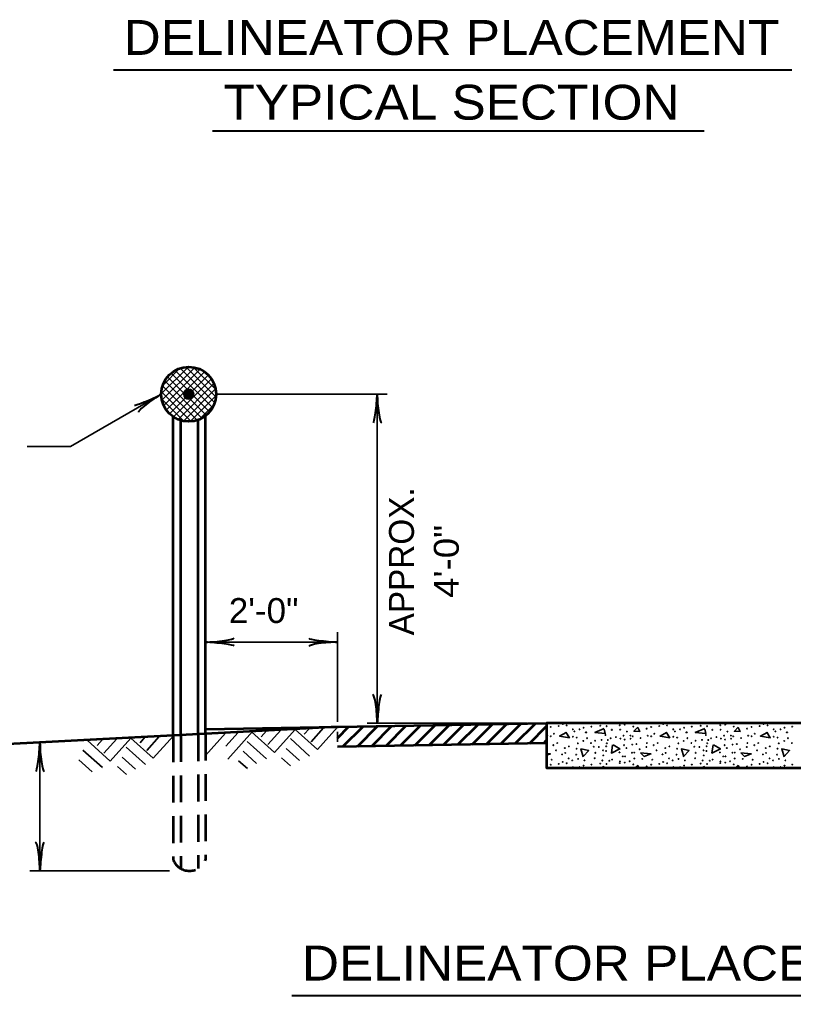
# Model space of a CAD drawing. Extents: x -54 to 626, y -41 to 399.
# Drawn here: x 39.2 to 116.9, y 192.7 to 290.7 of the extents above; entities that cross this region are included whole.
import ezdxf
from ezdxf.enums import TextEntityAlignment as Align

# ---------------------------------------------------------------- set-up
doc = ezdxf.new("R2010")
doc.units = 0
doc.header["$LTSCALE"] = 0.9
doc.linetypes.add('MEDIUM_DASHED', pattern=[4.5, 3, -1.5])
doc.layers.add('1', color=7, linetype='Continuous', lineweight=35)

msp = doc.modelspace()

# ---------------------------------------------------------------- hatches: boundary and pattern name
at = {"layer": '1'}
msp.add_hatch(color=256, dxfattribs=at).paths.add_polyline_path([(56.6827, 253.0622, 1), (55.6827, 253.0622, 1)])

# ---------------------------------------------------------------- linework, layer by layer
at = {"layer": '1', "lineweight": 40}
for p, q in [((48.6275, 285.6172), (116.6877, 285.6172)), ((58.5788, 279.5087), (107.9091, 279.5087)), ((66.5198, 192.7051), (134.58, 192.7051))]:
    msp.add_line(p, q, dxfattribs=at)
at = {"layer": '1'}
for p, q in [((53.4336, 253.0907), (56.153, 255.8101)), ((53.5029, 252.4528), (56.7912, 255.7412)), ((58.9153, 252.7899), (55.9091, 255.796)), ((58.8888, 253.5233), (56.6437, 255.7686)), ((53.5838, 253.948), (55.2978, 255.6619)), ((53.6836, 251.9264), (57.3184, 255.5613)), ((53.9397, 251.4755), (57.7702, 255.3059)), ((57.932, 250.9447), (54.0658, 254.8108)), ((54.2669, 251.0956), (58.1491, 254.9777)), ((58.2862, 251.2975), (54.4172, 255.1667)), ((58.5766, 251.7143), (54.8357, 255.4552)), ((58.7911, 252.2069), (55.327, 255.671)), ((58.2694, 254.8499), (57.9722, 255.1471)), ((57.016, 250.4465), (53.5672, 253.8953)), ((57.5109, 250.6586), (53.7781, 254.3915)), ((54.6566, 250.7782), (58.4674, 254.589)), ((55.1167, 250.5312), (58.7132, 254.1277)), ((56.429, 250.3264), (53.4478, 253.3075)), ((55.6601, 250.3674), (58.8776, 253.5849)), ((56.3205, 250.3207), (58.9248, 252.9251)), ((58.9327, 253.0622), (76.1023, 253.0622)), ((75.1023, 220.0399), (75.1023, 253.0622)), ((55.6857, 250.3625), (53.483, 252.5652)), ((57.2318, 250.5249), (58.7233, 252.0164)), ((71.1055, 220.1734), (71.1055, 229.1734)), ((71.1055, 228.1734), (57.8781, 228.1734)), ((68.2715, 219.4848), (67.7794, 218.9383)), ((69.7095, 219.5602), (68.4604, 218.1729)), ((71.1276, 219.6345), (69.1025, 217.3854)), ((90.1023, 220.0399), (74.1023, 220.0399)), ((48.958, 218.4725), (47.6521, 217.0222)), ((50.376, 218.5468), (48.3142, 216.2357)), ((50.376, 218.5468), (52.6251, 216.5217)), ((51.7941, 218.6212), (51.302, 218.0747)), ((53.2321, 218.6965), (51.983, 217.3092)), ((54.6502, 218.7708), (52.6251, 216.5217)), ((59.883, 219.0452), (57.8579, 216.7961)), ((61.1612, 219.1122), (59.9122, 217.7249)), ((62.5793, 219.1865), (60.1, 216.433)), ((62.4794, 219.1813), (64.7916, 217.0994)), ((63.9973, 219.2608), (63.4685, 218.6523)), ((65.4354, 219.3362), (64.1295, 217.8858)), ((66.8534, 219.4105), (64.7916, 217.0994)), ((66.3812, 218.4845), (68.315, 216.7433)), ((66.8534, 219.4105), (69.1025, 217.3854)), ((71.1055, 219.1734), (71.1055, 218.1731)), ((41.2531, 205.214), (41.2531, 218.0564)), ((46.002, 218.3176), (48.3142, 216.2357)), ((47.5199, 218.3972), (46.9911, 217.7887)), ((49.9038, 217.6208), (51.8376, 215.8797)), ((62.0503, 218.1975), (64.0041, 216.4573)), ((65.9721, 217.5017), (67.3173, 216.2905)), ((45.5729, 217.3338), (47.5267, 215.5937)), ((49.4947, 216.6381), (50.8399, 215.4268)), ((61.6412, 217.2147), (62.9864, 216.0034)), ((65.501, 216.5558), (66.4048, 215.742)), ((45.1638, 216.351), (46.509, 215.1397)), ((49.0236, 215.6922), (49.9274, 214.8783)), ((61.1901, 216.2698), (62.0928, 215.4759)), ((97.8798, 215.6893), (97.5102, 215.5399)), ((97.9035, 215.5399), (97.8798, 215.6493)), ((101.2398, 215.8293), (100.9648, 215.5399)), ((101.3644, 215.5399), (101.2398, 215.7893)), ((107.9597, 215.6893), (107.5902, 215.5399)), ((107.9835, 215.5399), (107.9597, 215.6493)), ((111.3197, 215.8293), (111.0448, 215.5399)), ((111.4444, 215.5399), (111.3197, 215.7893)), ((54.2531, 205.214), (40.2531, 205.214))]:
    msp.add_line(p, q, dxfattribs=at)
at = {"layer": '1', "lineweight": 53}
for p, q in [((54.6281, 218.8098), (54.6281, 250.7938)), ((57.8781, 218.9802), (57.8781, 250.8971)), ((55.3781, 218.8492), (55.3781, 250.4326)), ((57.1281, 218.9408), (57.1281, 250.4798)), ((57.8781, 219.4425), (92.1023, 220.0399)), ((71.1055, 218.5373), (72.2617, 219.6936)), ((71.6652, 217.6828), (73.7011, 219.7188)), ((73.1045, 217.708), (75.1404, 219.7438)), ((74.5439, 217.7331), (76.5798, 219.769)), ((75.9832, 217.7583), (78.0191, 219.7941)), ((77.4226, 217.7833), (79.4584, 219.8192)), ((78.8619, 217.8085), (80.8978, 219.8443)), ((80.3012, 217.8336), (82.3371, 219.8695)), ((81.7406, 217.8587), (83.7764, 219.8946)), ((83.1799, 217.8838), (85.2157, 219.9197)), ((84.6192, 217.909), (86.6551, 219.9448)), ((86.0586, 217.9341), (88.0944, 219.97)), ((87.4979, 217.9592), (89.5337, 219.9951)), ((88.9372, 217.9843), (90.9731, 220.0202)), ((90.3766, 218.0095), (92.1023, 219.7352)), ((54.6281, 218.8097), (15.6813, 216.7685)), ((92.1023, 218.0396), (71.1055, 217.6731)), ((91.8159, 218.0346), (92.1023, 218.321))]:
    msp.add_line(p, q, dxfattribs=at)
at = {"layer": '1', "linetype": 'MEDIUM_DASHED', "lineweight": 53}
for p, q in [((54.6281, 218.8098), (54.6281, 206.3098)), ((55.3781, 218.8492), (55.3781, 205.4481)), ((57.1281, 218.9408), (57.1281, 205.4481)), ((57.8781, 218.9802), (57.8781, 206.3098))]:
    msp.add_line(p, q, dxfattribs=at)
at = {"layer": '1'}
for points in [[(53.4327, 253.0622), (44.3074, 247.8093), (39.9817, 247.8093)], [(97.8798, 219.4893), (96.9398, 219.1093), (97.9797, 218.9893), (97.8798, 219.4493)], [(101.2398, 219.6293), (100.8597, 219.2293), (101.4398, 219.1893), (101.2398, 219.5893)], [(107.9597, 219.4893), (107.0198, 219.1093), (108.0597, 218.9893), (107.9597, 219.4493)], [(111.3197, 219.6293), (110.9397, 219.2293), (111.5198, 219.1893), (111.3197, 219.5893)], [(94.0597, 219.1093), (93.3997, 218.7493), (94.3798, 218.5693), (94.0198, 219.1293)], [(104.1397, 219.1093), (103.4797, 218.7493), (104.4597, 218.5693), (104.0998, 219.1293)], [(114.2197, 219.1093), (113.5597, 218.7493), (114.5397, 218.5693), (114.1797, 219.1293)], [(98.7597, 217.8493), (99.4597, 217.4493), (98.5998, 217.0293), (98.7197, 217.8693)], [(108.8397, 217.8493), (109.5397, 217.4493), (108.6797, 217.0293), (108.7998, 217.8693)], [(92.1023, 216.9929), (92.4797, 216.9493), (92.1023, 216.8162)], [(95.7797, 216.6493), (95.5397, 217.4493), (96.3197, 217.2893), (95.7597, 216.6893)], [(105.8597, 216.6493), (105.6197, 217.4493), (106.3997, 217.2893), (105.8397, 216.6893)], [(115.9397, 216.6493), (115.6997, 217.4493), (116.4797, 217.2893), (115.9197, 216.6893)]]:
    msp.add_lwpolyline(points, dxfattribs=at)
at = {"layer": '1', "lineweight": 53}
for points in [[(71.1055, 219.6734), (57.8781, 218.9802), (54.6281, 218.8097), (45.6523, 218.3393)], [(163.6023, 220.0399), (92.1023, 220.0399), (92.1023, 218.0396), (92.1023, 215.5399), (163.6023, 215.5399)]]:
    msp.add_lwpolyline(points, dxfattribs=at)
at = {"layer": '1'}
for points in [[(101.5198, 217.0693), (102.5597, 216.9493), (101.8798, 216.7093)], [(111.5998, 217.0693), (112.6397, 216.9493), (111.9597, 216.7093)]]:
    msp.add_lwpolyline(points, close=True, dxfattribs=at)
at = {"layer": '1', "lineweight": 53}
msp.add_circle((56.1827, 253.0622), 2.75, dxfattribs=at)
at = {"layer": '1'}
for centre, radius in [((56.1827, 253.0622), 0.5), ((92.5079, 219.66), 0.0265), ((93.3163, 219.7528), 0.0265), ((93.7139, 219.9469), 0.0265), ((94.1115, 219.8191), 0.0265), ((94.7343, 219.4214), 0.0265), ((95.4103, 219.4214), 0.0265), ((95.8079, 219.5805), 0.0265), ((96.5898, 219.6865), 0.0265), ((97.4778, 219.7794), 0.0265), ((98.1139, 219.7395), 0.0265), ((99.4392, 219.8324), 0.0265), ((99.4525, 219.9999), 0.0265), ((99.9428, 219.8854), 0.0265), ((100.4332, 220.0131), 0.0265), ((100.7987, 219.6998), 0.0265), ((102.1372, 219.4877), 0.0265), ((102.5879, 219.66), 0.0265), ((103.3963, 219.7528), 0.0265), ((103.7939, 219.9469), 0.0265), ((104.1915, 219.8191), 0.0265), ((104.8143, 219.4214), 0.0265), ((105.4903, 219.4214), 0.0265), ((105.8879, 219.5805), 0.0265), ((106.6698, 219.6865), 0.0265), ((107.5578, 219.7794), 0.0265), ((108.1939, 219.7395), 0.0265), ((109.5192, 219.8324), 0.0265), ((109.5325, 219.9999), 0.0265), ((110.0228, 219.8854), 0.0265), ((110.5132, 220.0131), 0.0265), ((110.8787, 219.6998), 0.0265), ((112.2172, 219.4877), 0.0265), ((112.6679, 219.66), 0.0265), ((113.4763, 219.7528), 0.0265), ((113.8739, 219.9469), 0.0265), ((114.2715, 219.8191), 0.0265), ((114.8943, 219.4214), 0.0265), ((115.5703, 219.4214), 0.0265), ((115.9679, 219.5805), 0.0265), ((116.7498, 219.6865), 0.0265), ((92.1632, 218.7718), 0.0265), ((92.5079, 218.732), 0.0265), ((92.8259, 218.9707), 0.0265), ((94.7344, 218.679), 0.0265), ((94.8934, 219.2092), 0.0265), ((95.1187, 218.5862), 0.0265), ((96.0332, 219.1165), 0.0265), ((96.0862, 219.1165), 0.0265), ((96.1525, 218.5331), 0.0265), ((98.0079, 218.8513), 0.0265), ((98.5247, 218.5199), 0.0265), ((98.644, 219.3683), 0.0265), ((99.0549, 218.6392), 0.0265), ((99.479, 219.3816), 0.0265), ((99.5055, 218.4934), 0.0265), ((99.8235, 218.785), 0.0265), ((100.1549, 219.1961), 0.0265), ((100.5128, 218.7983), 0.0265), ((100.5259, 218.4801), 0.0265), ((100.7457, 218.7188), 0.0265), ((101.5276, 218.5464), 0.0265), ((102.2432, 218.7718), 0.0265), ((102.5879, 218.732), 0.0265), ((102.9059, 218.9707), 0.0265), ((104.8144, 218.679), 0.0265), ((104.9734, 219.2092), 0.0265), ((105.1987, 218.5862), 0.0265), ((106.1132, 219.1165), 0.0265), ((106.1662, 219.1165), 0.0265), ((106.2325, 218.5331), 0.0265), ((108.0879, 218.8513), 0.0265), ((108.6047, 218.5199), 0.0265), ((108.724, 219.3683), 0.0265), ((109.1349, 218.6392), 0.0265), ((109.559, 219.3816), 0.0265), ((109.5855, 218.4934), 0.0265), ((109.9035, 218.785), 0.0265), ((110.2349, 219.1961), 0.0265), ((110.5928, 218.7983), 0.0265), ((110.6059, 218.4801), 0.0265), ((110.8257, 218.7188), 0.0265), ((111.6076, 218.5464), 0.0265), ((112.3232, 218.7718), 0.0265), ((112.6679, 218.732), 0.0265), ((112.9859, 218.9707), 0.0265), ((114.8944, 218.679), 0.0265), ((115.0534, 219.2092), 0.0265), ((115.2787, 218.5862), 0.0265), ((116.1932, 219.1165), 0.0265), ((116.2462, 219.1165), 0.0265), ((116.3125, 218.5331), 0.0265), ((92.7729, 217.8306), 0.0265), ((93.1705, 218.0427), 0.0265), ((93.9259, 217.5388), 0.0265), ((94.3367, 217.7112), 0.0265), ((95.1054, 217.4725), 0.0265), ((95.238, 218.0161), 0.0265), ((95.7814, 218.2548), 0.0265), ((96.5501, 218.0427), 0.0265), ((96.8283, 217.6715), 0.0265), ((96.9609, 218.268), 0.0265), ((97.3452, 217.6449), 0.0265), ((97.6103, 218.3608), 0.0265), ((98.0742, 217.7245), 0.0265), ((98.1404, 218.0294), 0.0265), ((98.2464, 218.3476), 0.0265), ((99.8765, 217.8306), 0.0265), ((99.9296, 218.3873), 0.0265), ((100.1019, 217.5388), 0.0265), ((100.685, 217.8836), 0.0265), ((101.1034, 217.9366), 0.0265), ((102.1108, 217.6449), 0.0265), ((102.1637, 218.0427), 0.0265), ((102.8529, 217.8306), 0.0265), ((103.2505, 218.0427), 0.0265), ((104.0059, 217.5388), 0.0265), ((104.4167, 217.7112), 0.0265), ((105.1854, 217.4725), 0.0265), ((105.318, 218.0161), 0.0265), ((105.8614, 218.2548), 0.0265), ((106.6301, 218.0427), 0.0265), ((106.9083, 217.6715), 0.0265), ((107.0409, 218.268), 0.0265), ((107.4252, 217.6449), 0.0265), ((107.6903, 218.3608), 0.0265), ((108.1542, 217.7245), 0.0265), ((108.2204, 218.0294), 0.0265), ((108.3264, 218.3476), 0.0265), ((109.9565, 217.8306), 0.0265), ((110.0096, 218.3873), 0.0265), ((110.1819, 217.5388), 0.0265), ((110.765, 217.8836), 0.0265), ((111.1834, 217.9366), 0.0265), ((112.1908, 217.6449), 0.0265), ((112.2437, 218.0427), 0.0265), ((112.9329, 217.8306), 0.0265), ((113.3305, 218.0427), 0.0265), ((114.0859, 217.5388), 0.0265), ((114.4967, 217.7112), 0.0265), ((115.2654, 217.4725), 0.0265), ((115.398, 218.0161), 0.0265), ((115.9414, 218.2548), 0.0265), ((116.7101, 218.0427), 0.0265), ((93.0512, 217.3134), 0.0265), ((93.6476, 216.9025), 0.0265), ((93.9657, 217.0483), 0.0265), ((94.3103, 216.5048), 0.0265), ((95.0657, 216.876), 0.0265), ((96.9212, 216.5181), 0.0265), ((96.9874, 217.0616), 0.0265), ((97.7693, 217.3134), 0.0265), ((97.7826, 216.7964), 0.0265), ((98.0609, 217.2472), 0.0265), ((99.4127, 217.1013), 0.0265), ((99.7441, 216.7036), 0.0265), ((99.9694, 216.7036), 0.0265), ((100.6653, 217.0726), 0.0265), ((100.8914, 217.0882), 0.0265), ((100.8914, 216.4915), 0.0265), ((101.4348, 217.4195), 0.0265), ((103.1312, 217.3134), 0.0265), ((103.7276, 216.9025), 0.0265), ((104.0457, 217.0483), 0.0265), ((104.3903, 216.5048), 0.0265), ((105.1457, 216.876), 0.0265), ((107.0012, 216.5181), 0.0265), ((107.0674, 217.0616), 0.0265), ((107.8493, 217.3134), 0.0265), ((107.8626, 216.7964), 0.0265), ((108.1409, 217.2472), 0.0265), ((109.4927, 217.1013), 0.0265), ((109.8241, 216.7036), 0.0265), ((110.0494, 216.7036), 0.0265), ((110.7453, 217.0726), 0.0265), ((110.9714, 217.0882), 0.0265), ((110.9714, 216.4915), 0.0265), ((111.5148, 217.4195), 0.0265), ((113.2112, 217.3134), 0.0265), ((113.8076, 216.9025), 0.0265), ((114.1257, 217.0483), 0.0265), ((114.4703, 216.5048), 0.0265), ((115.2257, 216.876), 0.0265), ((92.5079, 215.86), 0.0265), ((92.6139, 216.3722), 0.0265), ((93.3163, 215.9528), 0.0265), ((93.7139, 216.1469), 0.0265), ((94.1115, 216.0191), 0.0265), ((94.6681, 216.3059), 0.0265), ((94.7343, 215.6214), 0.0265), ((95.2512, 216.4518), 0.0265), ((95.4103, 215.6214), 0.0265), ((95.8079, 215.7805), 0.0265), ((95.9007, 216.3059), 0.0265), ((96.5898, 215.8865), 0.0265), ((97.4778, 215.9794), 0.0265), ((97.6899, 216.2927), 0.0265), ((98.1139, 215.9395), 0.0265), ((98.3923, 216.2661), 0.0265), ((98.644, 215.5683), 0.0265), ((98.6706, 216.3854), 0.0265), ((99.4392, 216.0324), 0.0265), ((99.4525, 216.1999), 0.0265), ((99.479, 215.5816), 0.0265), ((99.9428, 216.0854), 0.0265), ((100.4332, 216.2131), 0.0265), ((100.7987, 215.8998), 0.0265), ((101.6999, 216.4518), 0.0265), ((102.1372, 215.6877), 0.0265), ((102.5879, 215.86), 0.0265), ((102.6939, 216.3722), 0.0265), ((103.3963, 215.9528), 0.0265), ((103.7939, 216.1469), 0.0265), ((104.1915, 216.0191), 0.0265), ((104.7481, 216.3059), 0.0265), ((104.8143, 215.6214), 0.0265), ((105.3312, 216.4518), 0.0265), ((105.4903, 215.6214), 0.0265), ((105.8879, 215.7805), 0.0265), ((105.9807, 216.3059), 0.0265), ((106.6698, 215.8865), 0.0265), ((107.5578, 215.9794), 0.0265), ((107.7699, 216.2927), 0.0265), ((108.1939, 215.9395), 0.0265), ((108.4723, 216.2661), 0.0265), ((108.724, 215.5683), 0.0265), ((108.7506, 216.3854), 0.0265), ((109.5192, 216.0324), 0.0265), ((109.5325, 216.1999), 0.0265), ((109.559, 215.5816), 0.0265), ((110.0228, 216.0854), 0.0265), ((110.5132, 216.2131), 0.0265), ((110.8787, 215.8998), 0.0265), ((111.7799, 216.4518), 0.0265), ((112.2172, 215.6877), 0.0265), ((112.6679, 215.86), 0.0265), ((112.7739, 216.3722), 0.0265), ((113.4763, 215.9528), 0.0265), ((113.8739, 216.1469), 0.0265), ((114.2715, 216.0191), 0.0265), ((114.8281, 216.3059), 0.0265), ((114.8943, 215.6214), 0.0265), ((115.4112, 216.4518), 0.0265), ((115.5703, 215.6214), 0.0265), ((115.9679, 215.7805), 0.0265), ((116.0607, 216.3059), 0.0265), ((116.7498, 215.8865), 0.0265)]:
    msp.add_circle(centre, radius, dxfattribs=at)
for centre, start, end in [((98.3923, 220.0661), 262.28656, 277.71344), ((108.4723, 220.0661), 262.28656, 277.71344), ((92.0837, 218.0427), 314.79633, 45.20368)]:
    msp.add_arc(centre, 0.0265, start, end, dxfattribs=at)
at = {"layer": '1', "linetype": 'MEDIUM_DASHED', "lineweight": 53}
msp.add_arc((56.2531, 206.9668), 1.7528, 202.01371, 337.98629, dxfattribs=at)
at = {"layer": '1', "lineweight": 40}
for centre, major_axis, ratio, start_param, end_param in [((52.356, 252.6866), (1.6099, 0.724), 0.07063, 3.1407148, 5.41811), ((52.356, 252.6866), (1.6099, 0.724), 0.07063, 3.1407148, 5.41811), ((52.6248, 252.2784), (1.4697, 1.0262), 0.122415, 0.8963533, 3.1415927), ((52.6248, 252.2784), (1.4697, 1.0262), 0.122415, 0.8963533, 3.1415927), ((74.8907, 251.9417), (0.1757, 1.7565), 0.07063, 3.1407148, 5.41811), ((75.3786, 251.9711), (-0.1562, 1.7857), 0.122415, 0.8963533, 3.1415927), ((58.9693, 228.4497), (-1.7857, -0.1562), 0.122415, 0.8963533, 3.1415927), ((69.985, 228.385), (1.7565, -0.1757), 0.07063, 3.1407148, 5.41811), ((58.9986, 227.9618), (-1.7565, 0.1757), 0.07063, 3.1407148, 5.41811), ((70.0143, 227.8971), (1.7857, 0.1562), 0.122415, 0.8963533, 3.1415927), ((74.826, 221.1311), (0.1562, -1.7857), 0.122415, 0.8963533, 3.1415927), ((75.3139, 221.1604), (-0.1757, -1.7565), 0.07063, 3.1407148, 5.41811), ((41.0415, 216.9359), (0.1757, 1.7565), 0.07063, 3.1407148, 5.41811), ((41.0415, 216.9359), (0.1757, 1.7565), 0.07063, 3.1407148, 5.41811), ((41.5294, 216.9652), (-0.1562, 1.7857), 0.122415, 0.8963533, 3.1415927), ((41.5294, 216.9652), (-0.1562, 1.7857), 0.122415, 0.8963533, 3.1415927), ((40.9768, 206.3052), (0.1562, -1.7857), 0.122415, 0.8963533, 3.1415927), ((41.4647, 206.3345), (-0.1757, -1.7565), 0.07063, 3.1407148, 5.41811)]:
    msp.add_ellipse(centre, major_axis=major_axis, ratio=ratio, start_param=start_param, end_param=end_param, dxfattribs=at)

# ---------------------------------------------------------------- texts
at = {"layer": '1', "width": 1.1}
for s, p in [('DELINEATOR PLACEMENT', (82.5526, 287.1172)), ('TYPICAL SECTION', (82.5527, 280.6172)), ('DELINEATOR PLACEMENT', (100.4449, 194.2051))]:
    msp.add_text(s, height=3.5, dxfattribs=at).set_placement(p, align=Align.CENTER)
at = {"layer": '1'}
msp.add_text('APPROX.', height=2.5, rotation=90, dxfattribs=at).set_placement((78.7834, 236.2825), align=Align.CENTER)
at = {"layer": '1', "width": 1.1}
msp.add_text('4\'-0"', height=2.5, rotation=90, dxfattribs=at).set_placement((83.2834, 236.2825), align=Align.CENTER)
at = {"layer": '1', "width": 1.05}
msp.add_text('2\'-0"', height=2.5, dxfattribs=at).set_placement((60.2077, 230.0927))

doc.saveas('drawing.dxf')
